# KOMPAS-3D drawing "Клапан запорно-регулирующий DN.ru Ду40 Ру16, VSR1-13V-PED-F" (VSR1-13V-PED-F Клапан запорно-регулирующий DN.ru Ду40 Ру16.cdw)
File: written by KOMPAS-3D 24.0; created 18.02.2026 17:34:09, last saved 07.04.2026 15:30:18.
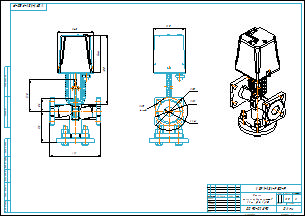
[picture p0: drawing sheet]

Document properties: Автор: R2D2; Форматы листов документа: A2; Полное имя файла: VSR1-13V-PED-F Клапан запорно-регулирующий DN.ru Ду40 Ру16.m3d; Масса: 10.5; Наименование: Клапан запорно-регулирующий DN.ru Ду40 Ру16; Количество листов документа: 1; Примечание: D090-02890

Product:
- Part/product: Клапан запорно-регулирующий DN.ru Ду40 Ру16  | designation VSR1-13V-PED-F
    Масса: 10.5
    Раздел спецификации: Прочие изделия
    Примечание: D090-02890

Views: Вид 1, Спереди
Referenced files in E:\Работа\Зайцев\Солянка\VSR1-13V-PED-F Клапан запорно-регулирующий DN.ru\DN15\DN15 Kv0.16\: VSR1-13V-PED-F Клапан запорно-регулирующий DN.ru Ду15 Ру16.m3d
Referenced files in E:\Работа\Зайцев\Солянка\VSR1-13V-PED-F Клапан запорно-регулирующий DN.ru\DN40\: VSR1-13V-PED-F Клапан запорно-регулирующий DN.ru Ду40 Ру16.m3d
Referenced files in E:\Работа\Зайцев\Для компаса\: чертеж DN.ru А3.cdt
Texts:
  Линейный размер
  VSR1-13V-PED-F
  чертеж DN.ru А3.cdt
  Клапан
  запорно-регулирующий
  DN.ru Ду40 Ру16
  Клапан запорно-регулирующий DN.ru Ду40 Ру16
  VSR1-13V-PED-F Клапан запорно-регулирующий DN.ru Ду40 Ру16
Dimensions and other numbers on the sheet: 0; 3; 2; 4; 143; 144; 269; 200; 120; 50; 125; 1:2; 1; 10,5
